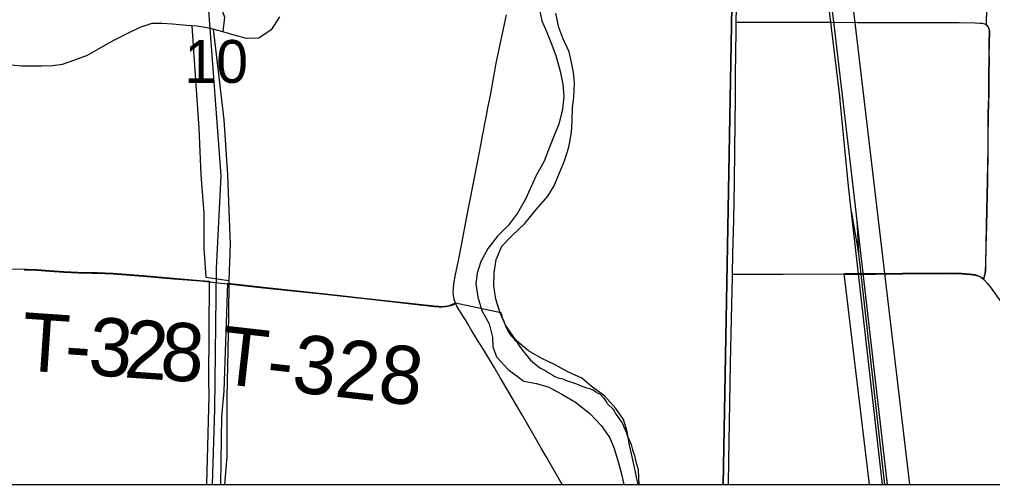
# Model space of a CAD drawing. Extents: x 0 to 34, y 0 to 22.
# Drawn here: x 4.727 to 5.678, y 14.1 to 14.554 of the extents above; entities that cross this region are included whole.
import ezdxf

# ---------------------------------------------------------------- set-up
doc = ezdxf.new("R2010")
doc.units = 0
for name, color, linetype in [('GM_X_City_Street', 7, 'Continuous'), ('GM_X_County_Road', 7, 'Continuous'), ('GM_X_Major_River', 7, 'Continuous'), ('GM_X_Minor_River', 7, 'Continuous'), ('GM_X_Rail_Line', 7, 'Continuous'), ('GM_X_Section_Text', 7, 'Continuous'), ('GM_X_Township_Road', 7, 'Continuous'), ('GM_X_Township_Road_Text', 7, 'Continuous'), ('GM_X_US_Route', 7, 'Continuous'), ('SH_Cut_Line', 7, 'Continuous'), ('SH_Data', 7, 'Continuous')]:
    doc.layers.add(name, color=color, linetype=linetype)

msp = doc.modelspace()

# ---------------------------------------------------------------- linework, layer by layer
at = {"layer": 'GM_X_City_Street'}
for points in [[(4.4112, 14.1), (5.41501, 14.1), (5.43209, 15.05104), (4.99489, 15.06466), (4.42986, 15.0671)], [(5.41501, 14.1), (6.40821, 14.1), (6.42317, 15.0563), (5.43209, 15.05104)]]:
    msp.add_lwpolyline(points, close=True, dxfattribs=at)
msp.add_lwpolyline([(5.42768, 14.55164), (5.43117, 14.55164), (5.44383, 14.55167), (5.4562, 14.55152), (5.47634, 14.55169), (5.48409, 14.55162), (5.49803, 14.55159), (5.50886, 14.55156), (5.52125, 14.55146), (5.54605, 14.55128), (5.58017, 14.55115), (5.5988, 14.55123), (5.61742, 14.55111), (5.64537, 14.55109), (5.66091, 14.55095), (5.6656, 14.5507), (5.66802, 14.55056), (5.67049, 14.55007), (5.67234, 14.54883)], dxfattribs=at)
at = {"layer": 'GM_X_County_Road'}
for points in [[(5.42768, 14.55164), (5.42879, 14.60678), (5.42897, 14.62602)], [(5.1535, 14.27697), (5.15226, 14.28079), (5.15153, 14.28498), (5.1513, 14.28832), (5.15134, 14.29132), (5.15191, 14.29588), (5.15355, 14.305), (5.1559, 14.31719), (5.15963, 14.33546), (5.16398, 14.35834), (5.16771, 14.37816), (5.1748, 14.41467), (5.17823, 14.43138), (5.17978, 14.44055), (5.18099, 14.44661), (5.18214, 14.45266), (5.18297, 14.45723), (5.18358, 14.46025), (5.1851, 14.4678), (5.1875, 14.47992), (5.18882, 14.4875), (5.19014, 14.49499), (5.19213, 14.5056), (5.1933, 14.51168), (5.19517, 14.52079), (5.19704, 14.52989), (5.20142, 14.54955), (5.20332, 14.55863)], [(5.42414, 14.30551), (5.42453, 14.32545), (5.42521, 14.35809), (5.42586, 14.39539), (5.4264, 14.42647), (5.42684, 14.47777), (5.4271, 14.50109), (5.42744, 14.51974), (5.42754, 14.54461), (5.42768, 14.55164)], [(5.42028, 14.1), (5.42052, 14.12339), (5.42111, 14.16069), (5.42195, 14.21822), (5.42297, 14.26173), (5.42326, 14.27572), (5.42407, 14.30214), (5.42414, 14.30551)], [(5.25757, 14.1), (5.24186, 14.1274), (5.23727, 14.13543), (5.2304, 14.14753), (5.21785, 14.16898), (5.20442, 14.19174), (5.19744, 14.20383), (5.19119, 14.21459), (5.18075, 14.23188), (5.17502, 14.24111), (5.16857, 14.25171), (5.16544, 14.25703), (5.16318, 14.261), (5.16072, 14.26492), (5.15901, 14.26751), (5.15666, 14.27101), (5.15473, 14.27425), (5.1535, 14.27697)]]:
    msp.add_lwpolyline(points, dxfattribs=at)
at = {"layer": 'GM_X_Major_River'}
for points in [[(4.98163, 14.5567), (4.97336, 14.544), (4.96142, 14.53594), (4.94929, 14.53547), (4.93726, 14.5388), (4.92598, 14.54211), (4.91281, 14.54584), (4.90112, 14.54764), (4.89091, 14.54827), (4.87694, 14.54975), (4.86673, 14.55037), (4.85688, 14.55023), (4.84504, 14.54634), (4.83239, 14.5402), (4.82012, 14.53404), (4.80668, 14.5264), (4.79362, 14.51913), (4.78139, 14.51449), (4.76916, 14.51023), (4.75967, 14.50894), (4.74905, 14.50844), (4.73921, 14.50868), (4.72936, 14.50854), (4.71652, 14.50998)], [(5.23587, 14.56231), (5.23791, 14.55277), (5.2422, 14.54242), (5.24683, 14.53092), (5.25146, 14.51905), (5.25563, 14.50376), (5.25834, 14.49117), (5.25918, 14.47901), (5.25811, 14.46651), (5.25425, 14.45182), (5.2499, 14.4409), (5.24538, 14.42961), (5.24019, 14.41571), (5.23227, 14.40186), (5.22627, 14.38872), (5.22185, 14.37858), (5.21394, 14.36511), (5.20531, 14.35317), (5.19445, 14.34243), (5.18545, 14.33088), (5.17831, 14.31777), (5.17462, 14.30648), (5.17323, 14.29626), (5.17517, 14.28294), (5.17902, 14.26994), (5.18626, 14.25686), (5.18973, 14.24387), (5.18987, 14.23438), (5.19342, 14.2248), (5.20485, 14.21238), (5.2201, 14.20101), (5.23254, 14.19881), (5.24457, 14.1951), (5.25727, 14.18834), (5.27071, 14.18043), (5.28483, 14.16946), (5.2959, 14.15781), (5.3043, 14.14546)], [(5.33183, 14.1), (5.33128, 14.10306), (5.32821, 14.11679), (5.32619, 14.12709), (5.32311, 14.14007), (5.32113, 14.15188), (5.31744, 14.1636), (5.30994, 14.17416), (5.29926, 14.18619), (5.28589, 14.19623), (5.27697, 14.20381), (5.26312, 14.21021), (5.25004, 14.21736), (5.23768, 14.22297), (5.22462, 14.2305), (5.21275, 14.24066), (5.20214, 14.25572), (5.19713, 14.2676), (5.19292, 14.28099), (5.19097, 14.29394), (5.19129, 14.30683), (5.19312, 14.31969), (5.19875, 14.33284), (5.20847, 14.34285), (5.22127, 14.35507), (5.23259, 14.36883), (5.24351, 14.38147), (5.24981, 14.39157), (5.25505, 14.40434), (5.25989, 14.41599), (5.26401, 14.42955), (5.26669, 14.44383), (5.26729, 14.4549), (5.26762, 14.46818), (5.269, 14.47801), (5.26974, 14.49242), (5.26884, 14.5023), (5.26682, 14.51222), (5.26442, 14.52253), (5.25832, 14.53596), (5.25441, 14.5463), (5.25135, 14.56041)], [(5.3043, 14.14546), (5.30859, 14.13511), (5.3128, 14.12134), (5.31589, 14.10874), (5.31773, 14.1)]]:
    msp.add_lwpolyline(points, dxfattribs=at)
at = {"layer": 'GM_X_Minor_River'}
for points in [[(4.99787, 14.58488), (4.98276, 14.58703), (4.96946, 14.58508), (4.95684, 14.58007), (4.94357, 14.57963), (4.9318, 14.5784), (4.9236, 14.56835), (4.92785, 14.55648), (4.92598, 14.54211)], [(4.89588, 14.54797), (4.8997, 14.49037), (4.90282, 14.44817), (4.90472, 14.40258), (4.90757, 14.36494), (4.90748, 14.33078), (4.90944, 14.30265), (4.93207, 14.29938)], [(4.91661, 14.54476), (4.92192, 14.50084), (4.92726, 14.45631), (4.93084, 14.40233), (4.93188, 14.36776), (4.93317, 14.33501), (4.93207, 14.29938), (4.93171, 14.26523), (4.93098, 14.23109), (4.93, 14.18488), (4.93008, 14.12719), (4.9278, 14.1)]]:
    msp.add_lwpolyline(points, dxfattribs=at)
at = {"layer": 'GM_X_Rail_Line'}
for p, q in [((5.54734, 14.32554), (5.54021, 14.36744)), ((5.54734, 14.32554), (5.54582, 14.35826)), ((5.573, 14.1), (5.54734, 14.32554))]:
    msp.add_line(p, q, dxfattribs=at)
for points in [[(5.52924, 14.47676), (5.52063, 14.54602), (5.49588, 14.75034), (5.47254, 14.93707), (5.46204, 15.02053), (5.44606, 15.15601), (5.40276, 15.39823), (5.29611, 16.02283), (5.1204, 17.03872), (4.99088, 17.79465), (4.73679, 19.26608), (4.60728, 20.02779), (4.45754, 20.9)], [(5.57545, 14.1), (5.54201, 14.39148), (5.52413, 14.54376), (5.49835, 14.75063), (5.47501, 14.93738), (5.4645, 15.02083), (5.44852, 15.15637), (5.4052, 15.39866), (5.29856, 16.02325), (5.12285, 17.03914), (4.99333, 17.79507), (4.73924, 19.2665), (4.60973, 20.02821), (4.45756, 20.9)], [(5.50221, 14.74952), (5.51365, 14.74383), (5.5219, 14.73558), (5.59682, 14.1)], [(4.90666, 14.63728), (4.92432, 14.40144), (4.91951, 14.311), (4.91795, 14.17373), (4.91581, 14.1)], [(5.57052, 14.1), (5.53748, 14.39148), (5.52782, 14.48825)]]:
    msp.add_lwpolyline(points, dxfattribs=at)
at = {"layer": 'GM_X_Township_Road'}
for points in [[(4.67005, 14.31205), (4.73193, 14.31027), (4.73504, 14.31032), (4.74435, 14.31006), (4.75674, 14.3091), (4.77069, 14.30807), (4.78465, 14.30746), (4.80328, 14.30695), (4.8188, 14.30634), (4.84822, 14.30406), (4.87762, 14.30144), (4.90396, 14.29938), (4.91281, 14.29849), (4.91208, 14.20155), (4.91252, 14.18705), (4.9102, 14.1), (4.92412, 14.1), (4.92517, 14.16653), (4.92754, 14.19129), (4.93089, 14.29658), (4.96575, 14.2928), (5.026, 14.28633), (5.0785, 14.28049), (5.13255, 14.27438), (5.13719, 14.27405), (5.14028, 14.27402), (5.14336, 14.27433), (5.14748, 14.27493), (5.15056, 14.27604), (5.15328, 14.27752), (5.19774, 14.268), (5.19788, 14.26729), (5.19788, 14.2669), (5.19817, 14.2662), (5.19859, 14.26523), (5.19909, 14.2625), (5.19937, 14.26186), (5.20042, 14.26013), (5.20089, 14.2589), (5.20107, 14.25822), (5.2013, 14.25749), (5.20239, 14.25495), (5.20374, 14.25222), (5.20447, 14.25029), (5.20491, 14.24937), (5.20644, 14.24694), (5.20817, 14.24489), (5.21035, 14.24248), (5.21147, 14.24106), (5.2124, 14.24031), (5.21296, 14.23973), (5.21526, 14.23618), (5.2181, 14.23174), (5.22671, 14.22153), (5.2343, 14.21531), (5.23641, 14.21379), (5.23962, 14.21195), (5.24163, 14.21093), (5.24333, 14.20959), (5.24852, 14.20677), (5.25032, 14.20547), (5.2538, 14.20428), (5.25826, 14.20311), (5.26252, 14.20114), (5.26713, 14.19982), (5.27323, 14.1976), (5.27534, 14.19666), (5.28051, 14.19482), (5.28303, 14.19414), (5.28545, 14.19345), (5.28667, 14.19295), (5.28746, 14.19265), (5.28837, 14.19217), (5.29058, 14.19061), (5.29122, 14.19007), (5.2917, 14.18966), (5.29472, 14.18813), (5.29543, 14.18751), (5.29791, 14.18464), (5.30101, 14.18045), (5.30168, 14.17919), (5.30333, 14.17742), (5.30656, 14.17445), (5.30846, 14.17185), (5.31, 14.16878), (5.31195, 14.16597), (5.31408, 14.16308), (5.31526, 14.16165), (5.31589, 14.16049), (5.31726, 14.15838), (5.31767, 14.15709), (5.32053, 14.15062), (5.32117, 14.14819), (5.3215, 14.1471), (5.3228, 14.14437), (5.32501, 14.1392), (5.32639, 14.13391), (5.32828, 14.12825), (5.32924, 14.12352), (5.33134, 14.11711), (5.3318, 14.11404), (5.33257, 14.1), (5.55796, 14.1), (5.53301, 14.30604), (5.54794, 14.30604), (5.56358, 14.30615), (5.59015, 14.30638), (5.63392, 14.30661), (5.64794, 14.30633), (5.65568, 14.30577), (5.66123, 14.30499), (5.66449, 14.30393), (5.66696, 14.30261), (5.66942, 14.3008), (5.6708, 14.30636), (5.67118, 14.3092), (5.67142, 14.31475), (5.67175, 14.33334), (5.67219, 14.35354), (5.67324, 14.39701), (5.67365, 14.42808), (5.67369, 14.44362), (5.67389, 14.45602), (5.67396, 14.45757), (5.67393, 14.46222), (5.6742, 14.4715), (5.67438, 14.47768), (5.67449, 14.47922), (5.67452, 14.4823), (5.67451, 14.48845), (5.67456, 14.49312), (5.67451, 14.50244), (5.67474, 14.51483), (5.67465, 14.52263), (5.6748, 14.52878), (5.67494, 14.53498), (5.6752, 14.53927), (5.67508, 14.5431), (5.67459, 14.54582), (5.6736, 14.54754), (5.67211, 14.54939), (5.68051, 14.96162)], [(5.66965, 14.30025), (5.67103, 14.30581), (5.6714, 14.30865), (5.67164, 14.3142), (5.67198, 14.33279), (5.67242, 14.35298), (5.67347, 14.39646), (5.67388, 14.42753), (5.67392, 14.44307), (5.67412, 14.45547), (5.67418, 14.45702), (5.67416, 14.46166), (5.67443, 14.47095), (5.6746, 14.47712), (5.67471, 14.47867), (5.67475, 14.48174), (5.67473, 14.4879), (5.67479, 14.49257), (5.67474, 14.50188), (5.67497, 14.51428), (5.67488, 14.52208), (5.67502, 14.52822), (5.67517, 14.53442), (5.67543, 14.53872), (5.6753, 14.54255), (5.67481, 14.54526), (5.67382, 14.54698), (5.67234, 14.54883)], [(4.73216, 14.30972), (4.73526, 14.30977), (4.74458, 14.3095), (4.75697, 14.30854), (4.77091, 14.30752), (4.78487, 14.3069), (4.79833, 14.30654)], [(4.79833, 14.30654), (4.80351, 14.3064), (4.81902, 14.30579), (4.84845, 14.3035), (4.87785, 14.30089), (4.90418, 14.29883), (4.91303, 14.29793), (4.91394, 14.29784)], [(4.91394, 14.29784), (4.92118, 14.29711), (4.93111, 14.29603)], [(5.42414, 14.30551), (5.4283, 14.30554), (5.43587, 14.30561), (5.44216, 14.30538), (5.47346, 14.30552), (5.51254, 14.30569), (5.53323, 14.30549)], [(5.53323, 14.30549), (5.54817, 14.30549), (5.5638, 14.30559), (5.59037, 14.30583), (5.63414, 14.30606), (5.64816, 14.30577), (5.6559, 14.30522), (5.66146, 14.30444), (5.66471, 14.30337), (5.66718, 14.30206), (5.66965, 14.30025)], [(5.66965, 14.30025), (5.67294, 14.29679), (5.67671, 14.29162), (5.68227, 14.28407), (5.68493, 14.28025), (5.69677, 14.26389), (5.70577, 14.25122), (5.7139, 14.23986), (5.72865, 14.21986), (5.74153, 14.20231), (5.74874, 14.1922), (5.76138, 14.17452), (5.76981, 14.1634), (5.78231, 14.14754), (5.7889, 14.13889), (5.79726, 14.12769), (5.81049, 14.11046), (5.81855, 14.1)], [(4.93111, 14.29603), (4.96598, 14.29225), (5.02623, 14.28578), (5.07873, 14.27994), (5.13277, 14.27383), (5.13741, 14.2735), (5.14051, 14.27346), (5.14359, 14.27377), (5.1477, 14.27437), (5.15079, 14.27549), (5.1535, 14.27697)]]:
    msp.add_lwpolyline(points, dxfattribs=at)
at = {"layer": 'GM_X_US_Route'}
msp.add_lwpolyline([(3.40839, 14.1), (7.42441, 14.1)], dxfattribs=at)
at = {"layer": 'SH_Cut_Line'}
msp.add_lwpolyline([(2.1, 20.9), (2.1, 14.1), (7.42441, 14.1)], dxfattribs=at)
at = {"layer": 'SH_Data'}
msp.add_line((2.1, 14.1), (8.9, 14.1), dxfattribs=at)

# ---------------------------------------------------------------- texts
at = {"layer": 'GM_X_Section_Text'}
msp.add_text('10', height=0.041856, rotation=0.00001, dxfattribs=at).set_placement((4.88852, 14.49227))
at = {"layer": 'GM_X_Township_Road_Text'}
for s, height, rotation, p in [('T', 0.05682, 356.07988, (4.7281, 14.21164)), ('3', 0.05682, 356.08633, (4.7938, 14.20714)), ('2', 0.05682, 356.1312, (4.82877, 14.20474)), ('8', 0.05682, 356.32018, (4.8639, 14.20237)), ('T-328', 0.056818, 353.56786, (4.92103, 14.19882)), ('-', 0.05682, 356.06287, (4.7705, 14.20874))]:
    msp.add_text(s, height=height, rotation=rotation, dxfattribs=at).set_placement(p)

doc.saveas('drawing.dxf')
